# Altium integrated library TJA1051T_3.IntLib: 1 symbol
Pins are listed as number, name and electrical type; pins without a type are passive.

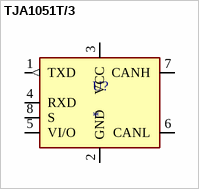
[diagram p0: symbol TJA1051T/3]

## TJA1051T/3
designator U?
1/1 ÐŸÑ€Ð¸ÐµÐ¼Ð¾Ð¿ÐµÑ€ÐµÐ´Ð°Ñ‚Ñ‡Ð¸Ðº ÐŸÐ¾Ð»Ð¾Ð²Ð¸Ð½Ð° CANbus 8-SO; MF: NXP USA; MP: TJA1051T/3
footprint SOT96-1
pins: 1 TXD (out), 2 GND (io), 3 VCC (io), 4 RXD (io), 5 VI/O, 6 CANL (io), 7 CANH (io), 8 S (power)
